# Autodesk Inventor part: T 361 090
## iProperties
Company: Mayer & Müller AG Schaltgeräte
Created: 2005-12
Part Number: T 361 090
Material: 1.0330
Document SubType Name: Sheet Metal
Designer: I.Baliuc
Manufacturer: Standard
Standards Organization: Custom
Description: Lasche
Density: 7.84 g/cm^3
Sheet Metal Rule: Standard
Zweck: Strombahn
Abmessung: Bl. 2x1000x2000
Author: T.Messerschmitt
Keywords: 266495
Revision Number: 361090
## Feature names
1. Bohrung1 [Hole]
2. Grobblech1
